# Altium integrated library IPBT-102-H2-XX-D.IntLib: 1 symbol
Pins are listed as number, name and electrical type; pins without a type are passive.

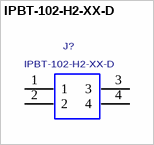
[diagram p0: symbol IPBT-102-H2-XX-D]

## IPBT-102-H2-XX-D
designator J?
0.165" DOUBLE ROW TERMINAL ASSEMBLY; MANUFACTURER: SAMTEC
footprint IPBT-102-H2-XX-D
pins: 1, 2, 3, 4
